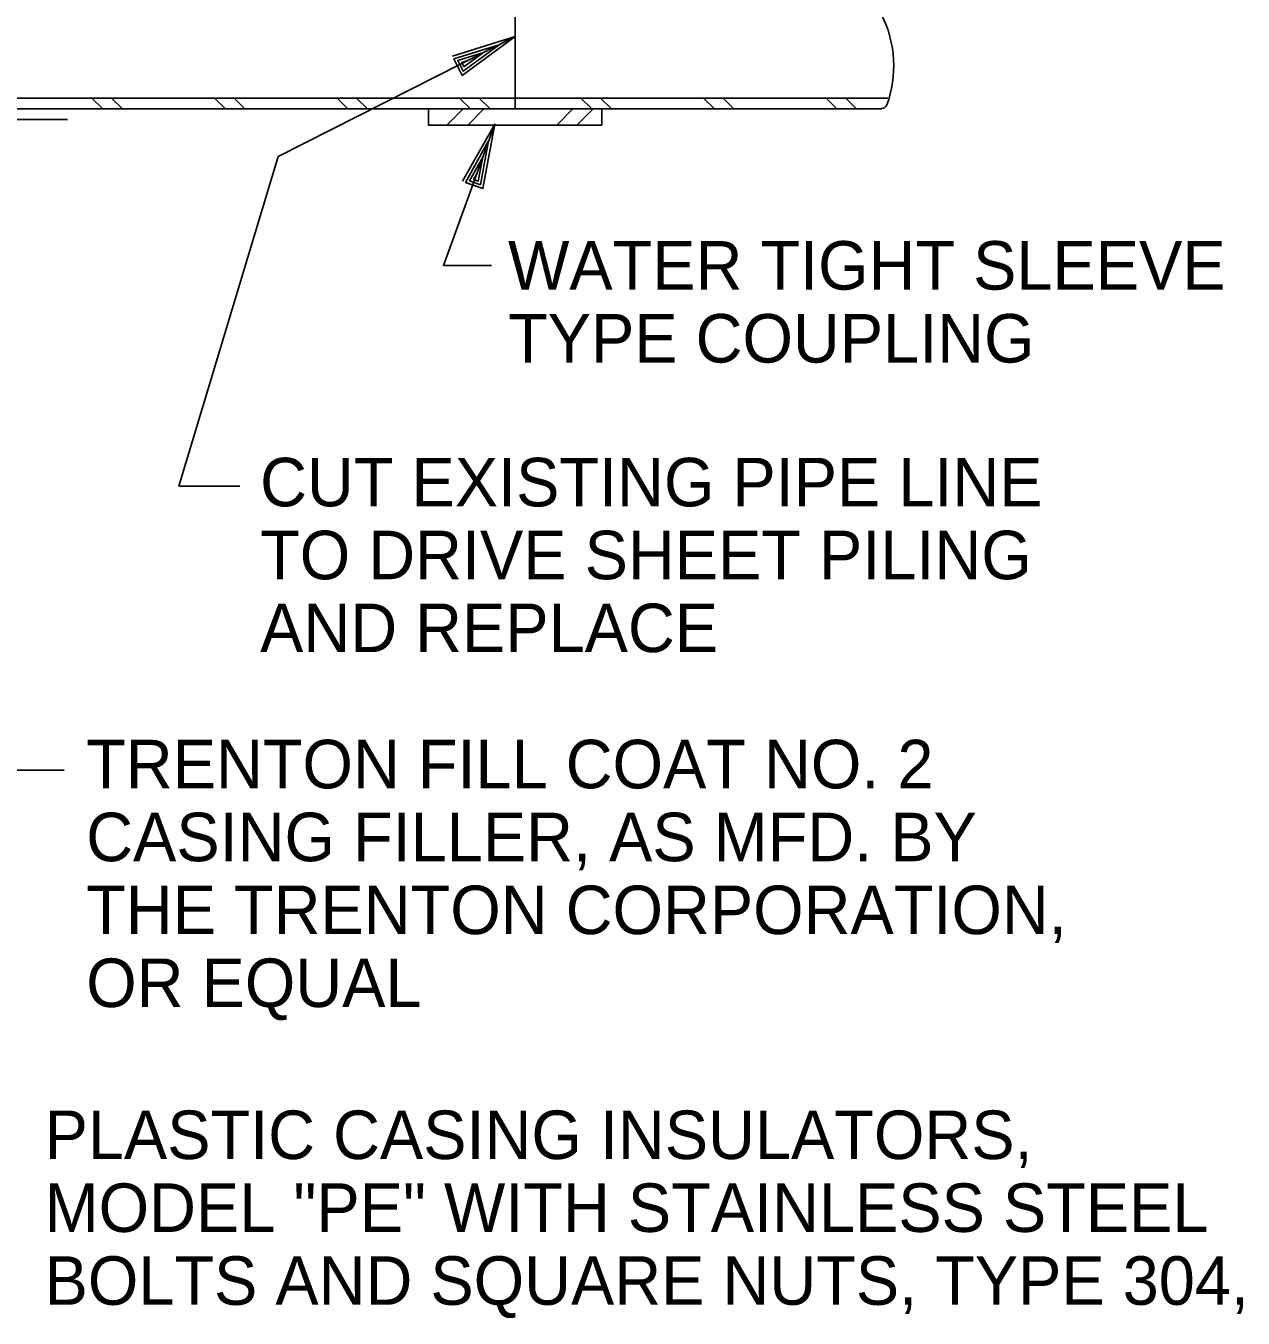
# Model space of a CAD drawing. Extents: x 22422.9 to 22498.9, y 22369.6 to 22415.
# Drawn here: x 22434.498 to 22439.181, y 22387.476 to 22392.447 of the extents above; entities that cross this region are included whole.
import ezdxf

# ---------------------------------------------------------------- set-up
doc = ezdxf.new("R2010")
doc.units = 0
for name, color, linetype in [('Level 1', 7, 'Continuous'), ('Level 2', 7, 'Continuous'), ('Level 4', 7, 'Continuous'), ('Level 7', 7, 'Continuous'), ('Level 8', 7, 'Continuous')]:
    doc.layers.add(name, color=color, linetype=linetype)

msp = doc.modelspace()

# ---------------------------------------------------------------- linework, layer by layer
at = {"layer": 'Level 1'}
for p, q in [((22436.3695, 22392.0291), (22436.3695, 22392.0291)), ((22436.333, 22391.9702), (22436.333, 22391.9702))]:
    msp.add_line(p, q, dxfattribs=at)
for centre, radius, start, end in [((22437.4009, 22392.2934), 0.4356, 339.8081, 26.6071), ((22437.7898, 22392.1504), 0.0213, 270, 339.6845)]:
    msp.add_arc(centre, radius, start, end, dxfattribs=at)
at = {"layer": 'Level 2'}
for p, q in [((22436.3804, 22392.1279), (22436.3804, 22392.8467)), ((22435.4681, 22391.9452), (22436.3802, 22392.4059)), ((22431.1304, 22392.1696), (22437.8136, 22392.1696)), ((22431.1304, 22392.1279), (22437.7901, 22392.1279)), ((22436.0471, 22392.0654), (22436.0471, 22392.1279)), ((22436.7137, 22392.0654), (22436.7137, 22392.1279)), ((22436.0471, 22392.0654), (22436.7137, 22392.0654)), ((22435.0858, 22390.6762), (22435.4681, 22391.9452)), ((22435.3205, 22390.6762), (22435.0858, 22390.6762))]:
    msp.add_line(p, q, dxfattribs=at)
for points in [[(22436.139, 22392.3304), (22436.3802, 22392.4059), (22436.1763, 22392.2566), (22436.1444, 22392.3197), (22436.3183, 22392.3746), (22436.1798, 22392.2733), (22436.1593, 22392.3138), (22436.2588, 22392.3446), (22436.1833, 22392.29), (22436.1749, 22392.3067), (22436.1969, 22392.3133)], [(22434.6451, 22389.5833), (22434.2976, 22389.5833), (22433.2205, 22392.0517)], [(22436.2896, 22391.5252), (22436.1043, 22391.5252), (22436.3016, 22392.0696)], [(22436.1778, 22391.8493), (22436.3016, 22392.0696), (22436.2555, 22391.8211), (22436.1891, 22391.8452), (22436.278, 22392.0044), (22436.2466, 22391.8357), (22436.204, 22391.8512), (22436.2552, 22391.9418), (22436.2377, 22391.8503), (22436.2201, 22391.8566), (22436.2316, 22391.8766)]]:
    msp.add_lwpolyline(points, dxfattribs=at)
at = {"layer": 'Level 7'}
msp.add_line((22434.3109, 22392.0863), (22434.6581, 22392.0863), dxfattribs=at)
at = {"layer": 'Level 8'}
for p, q in [((22436.3802, 22392.4059), (22436.3802, 22392.4059)), ((22436.3183, 22392.3746), (22436.3183, 22392.3746)), ((22436.3016, 22392.0696), (22436.3016, 22392.0696)), ((22436.278, 22392.0044), (22436.278, 22392.0044))]:
    msp.add_line(p, q, dxfattribs=at)
for points in [[(22434.7938, 22392.1279), (22434.7522, 22392.1696)], [(22434.8693, 22392.1279), (22434.8276, 22392.1696)], [(22435.2653, 22392.1279), (22435.2236, 22392.1696)], [(22435.3407, 22392.1279), (22435.299, 22392.1696)], [(22435.7367, 22392.1279), (22435.695, 22392.1696)], [(22435.8121, 22392.1279), (22435.7704, 22392.1696)], [(22436.1804, 22392.1279), (22436.1179, 22392.0654)], [(22436.2081, 22392.1279), (22436.1664, 22392.1696)], [(22436.2601, 22392.1279), (22436.1976, 22392.0654)], [(22436.2835, 22392.1279), (22436.2418, 22392.1696)], [(22436.6023, 22392.1279), (22436.5398, 22392.0654)], [(22436.6799, 22392.1279), (22436.6174, 22392.0654)], [(22436.675, 22392.1279), (22436.6333, 22392.1696)], [(22436.7504, 22392.1279), (22436.7087, 22392.1696)], [(22437.1464, 22392.1279), (22437.1047, 22392.1696)], [(22437.2218, 22392.1279), (22437.1801, 22392.1696)], [(22437.6178, 22392.1279), (22437.5761, 22392.1696)], [(22437.6932, 22392.1279), (22437.6515, 22392.1696)]]:
    msp.add_lwpolyline(points, dxfattribs=at)

# ---------------------------------------------------------------- texts
at = {"layer": 'Level 4'}
for s, height, p in [('WATER TIGHT SLEEVE', 0.186667, (22436.353, 22391.4324)), ('TYPE COUPLING ', 0.186667, (22436.353, 22391.1519)), ('CUT EXISTING PIPE LINE', 0.186667, (22435.399, 22390.5987)), ('TO DRIVE SHEET PILING', 0.186667, (22435.399, 22390.3183)), ('AND REPLACE', 0.186667, (22435.399, 22390.0379)), ('TRENTON FILL COAT NO. 2', 0.186667, (22434.73, 22389.514)), ('CASING FILLER, AS MFD. BY', 0.186667, (22434.73, 22389.2336)), ('THE TRENTON CORPORATION,', 0.186667, (22434.73, 22388.9532)), ('OR EQUAL', 0.18667, (22434.73, 22388.6727)), ('PLASTIC CASING INSULATORS,', 0.186667, (22434.5699, 22388.0879)), ('MODEL "PE" WITH STAINLESS STEEL', 0.186667, (22434.5699, 22387.8075)), ('BOLTS AND SQUARE NUTS, TYPE 304,', 0.186667, (22434.5699, 22387.5271))]:
    msp.add_text(s, height=height, dxfattribs=at).set_placement(p)

doc.saveas('drawing.dxf')
